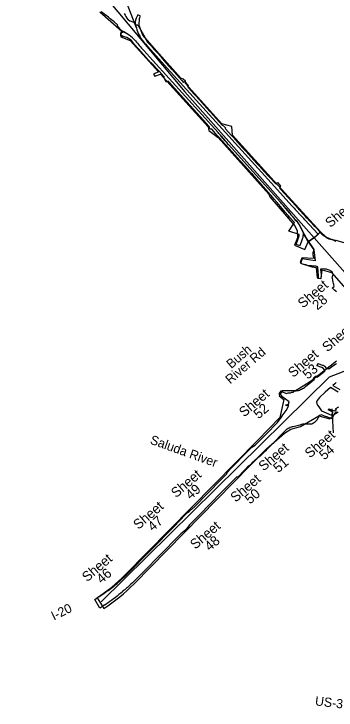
# Model space of a CAD drawing. Extents: x 1944182 to 1978751, y 789830 to 827717.
# Drawn here: x 1953823 to 1964336, y 789830 to 812550 of the extents above; entities that cross this region are included whole.
import ezdxf

# ---------------------------------------------------------------- set-up
doc = ezdxf.new("R2010")
doc.units = 0
for name, color, linetype in [('Default', 7, 'Continuous'), ('RD_AR_03', 7, 'Continuous'), ('RD_AR_04', 7, 'Continuous'), ('RD_AR_05', 7, 'Continuous'), ('RD_SHT_ID', 7, 'Continuous'), ('RD_SHT_Misc4', 7, 'Continuous')]:
    doc.layers.add(name, color=color, linetype=linetype)

msp = doc.modelspace()

# ---------------------------------------------------------------- linework, layer by layer
at = {"layer": 'Default'}
for points in [[(1964345, 803483), (1964330, 803497), (1964283, 803539), (1964264, 803556), (1964209, 803606), (1964271, 803655), (1964258, 803721), (1964252, 803748), (1964243, 803793), (1964239, 803809), (1964235, 803831), (1964230, 803856), (1964216, 803922), (1964213, 803938), (1964222, 803977), (1964238, 804046), (1964243, 804065), (1964231, 804078), (1964218, 804091), (1964219, 804117), (1964197, 804135), (1964170, 804154), (1964141, 804171), (1964112, 804186), (1964082, 804199), (1964050, 804209), (1964045, 804210), (1964018, 804217), (1963986, 804222), (1963953, 804225), (1963920, 804226), (1963887, 804224), (1963854, 804220), (1963830, 804215), (1963844, 804036), (1963845, 804010), (1963844, 803984), (1963841, 803958), (1963832, 803904), (1963752, 803910), (1963762, 803970), (1963764, 803990), (1963765, 804010), (1963765, 804010), (1963764, 804029), (1963755, 804138), (1963743, 804293), (1963673, 804320), (1963643, 804320), (1963643, 804320), (1963618, 804320), (1963563, 804322), (1963537, 804324), (1963509, 804327), (1963458, 804334), (1963454, 804334), (1963401, 804344), (1963379, 804349), (1963347, 804356), (1963294, 804370), (1963242, 804387), (1963191, 804406), (1963204, 804441), (1963204, 804442), (1963179, 804452), (1963230, 804604), (1963401, 804592), (1963624, 804575), (1963613, 804599), (1963604, 804623), (1963597, 804648), (1963592, 804673), (1963589, 804698), (1963588, 804724), (1963589, 804738), (1963590, 804750), (1963592, 804765), (1963593, 804775), (1963599, 804801), (1963607, 804825), (1963615, 804850), (1963619, 804865), (1963394, 805197), (1963391, 805201), (1963287, 805354), (1963268, 805382), (1963261, 805363), (1963259, 805330), (1963259, 805329), (1963255, 805296), (1963250, 805263), (1963248, 805256), (1963243, 805230), (1963234, 805197), (1963223, 805165), (1963156, 804983), (1963127, 804994), (1963070, 805014), (1963034, 805028), (1963101, 805210), (1963112, 805244), (1963120, 805278), (1963126, 805313), (1963130, 805348), (1962797, 805460), (1962974, 805742), (1962819, 805913), (1962789, 805947), (1962759, 805982), (1962760, 805982), (1962673, 806084), (1962521, 806262), (1962408, 806394), (1962315, 806503), (1962215, 806620), (1962176, 806666), (1962137, 806712), (1962122, 806729), (1962067, 806793), (1962035, 806831), (1962031, 806835), (1961892, 806994), (1961888, 806999), (1961876, 807013), (1961866, 807024), (1961853, 807039), (1961839, 807055), (1961827, 807067), (1961812, 807085), (1961797, 807102), (1961777, 807124), (1961748, 807157), (1961603, 807318), (1961567, 807358), (1961530, 807399), (1961476, 807459), (1961430, 807510), (1961380, 807565), (1961220, 807741), (1961109, 807865), (1961041, 807939), (1960517, 808519), (1960516, 808520), (1960458, 808584), (1960278, 808784), (1960242, 808786), (1960198, 808835), (1960200, 808870), (1960183, 808888), (1960011, 809078), (1960009, 809081), (1959467, 809680), (1959462, 809685), (1958977, 810222), (1958945, 810257), (1958939, 810263), (1958859, 810352), (1958812, 810329), (1958789, 810319), (1958712, 810475), (1958734, 810487), (1958736, 810488), (1958611, 810627), (1958601, 810637), (1958581, 810659), (1958560, 810682), (1958558, 810684), (1958544, 810700), (1958505, 810740), (1958365, 810883), (1958325, 810926), (1958323, 810928), (1958285, 810969), (1958060, 811217), (1958033, 811248), (1958030, 811251), (1957988, 811297), (1957967, 811320), (1957901, 811395), (1957873, 811426), (1957760, 811557), (1957728, 811594), (1957649, 811689), (1957503, 811783), (1957468, 811795), (1957433, 811805), (1957396, 811812), (1957359, 811817), (1957361, 811834), (1957338, 811837), (1957315, 811839), (1957317, 811936), (1957405, 811961), (1957377, 811979), (1957349, 811998), (1957323, 812020), (1957299, 812043), (1957275, 812067), (1957254, 812093), (1957234, 812120), (1957215, 812148), (1957202, 812195), (1957093, 812289), (1957093, 812289), (1956969, 812394), (1956908, 812446), (1956909, 812446), (1956670, 812621)], [(1957421, 812560), (1957448, 812511), (1957477, 812462), (1957507, 812415), (1957510, 812411), (1957539, 812368), (1957539, 812368), (1957558, 812357), (1957605, 812328), (1957616, 812321), (1957616, 812321), (1957776, 812259), (1957776, 812259), (1957776, 812259), (1957776, 812257), (1957775, 812233), (1957775, 812227), (1957777, 812191), (1957865, 812191), (1958047, 811871), (1958134, 811704), (1958185, 811631), (1958260, 811548), (1958297, 811508), (1958367, 811430), (1958383, 811411), (1958437, 811352), (1958537, 811242), (1958574, 811201), (1958594, 811178), (1958613, 811157), (1958643, 811121), (1958651, 811113), (1958685, 811072), (1958779, 810959), (1958815, 810917), (1958849, 810879), (1958853, 810875), (1958882, 810842), (1958979, 810735), (1958982, 810732), (1958983, 810731), (1959049, 810658), (1959303, 810377), (1959359, 810315), (1959359, 810315), (1959380, 810335), (1959396, 810349), (1959521, 810210), (1959484, 810177), (1959539, 810116), (1959601, 810047), (1959730, 809905), (1959887, 809731), (1959951, 809660), (1959952, 809660), (1960021, 809583), (1960219, 809364), (1960224, 809368), (1960260, 809320), (1960325, 809247), (1960620, 808921), (1960662, 808900), (1960727, 808829), (1960718, 808812), (1960924, 808585), (1960975, 808529), (1961297, 808173), (1961298, 808172), (1961330, 808137), (1961341, 808124), (1961403, 808056), (1961552, 807890), (1961760, 807660), (1961866, 807544), (1961870, 807539), (1961931, 807472), (1961960, 807440), (1961998, 807398), (1962000, 807397), (1962101, 807289), (1962185, 807200), (1962245, 807136), (1962286, 807092), (1962370, 807004), (1962375, 806998), (1962375, 806998), (1962426, 807044), (1962500, 806964), (1962524, 806938), (1962497, 806877), (1962503, 806857), (1962667, 806676), (1962773, 806559), (1962773, 806558), (1962812, 806516), (1962830, 806496), (1962905, 806413), (1963012, 806295), (1963089, 806209), (1963136, 806157), (1963138, 806156), (1963190, 806098), (1963193, 806095), (1963234, 806049), (1963241, 806041), (1963272, 806008), (1963289, 805989), (1963310, 805967), (1963354, 805920), (1963401, 805870), (1963455, 805812), (1963511, 805751), (1963551, 805708), (1963579, 805677), (1963646, 805603), (1963654, 805609), (1963689, 805568), (1963692, 805566), (1963731, 805521), (1963787, 805456), (1963808, 805432), (1963839, 805398), (1963871, 805366), (1963905, 805336), (1963923, 805322), (1963941, 805307), (1963978, 805281), (1964006, 805264), (1964017, 805257), (1964057, 805235), (1964098, 805215), (1964140, 805198), (1964183, 805183), (1964198, 805195), (1964322, 805139), (1964332, 805162), (1964626, 805081)], [(1964338, 799563), (1964320, 799548), (1964304, 799532), (1964290, 799514), (1964277, 799494), (1964266, 799474), (1964246, 799431), (1964204, 799340), (1964170, 799352), (1964168, 799347), (1964063, 799385), (1963958, 799426), (1963855, 799468), (1963788, 799442), (1963763, 799386), (1963749, 799357), (1963734, 799330), (1963716, 799304), (1963697, 799279), (1963676, 799256), (1963653, 799234), (1963629, 799214), (1963604, 799195), (1963577, 799178), (1963550, 799163), (1963363, 799165), (1963359, 799165), (1963277, 799162), (1963236, 799161), (1963208, 799149), (1963179, 799138), (1963150, 799129), (1962937, 799079), (1962902, 799071), (1962867, 799061), (1962833, 799049), (1962800, 799034), (1962768, 799017), (1962737, 798999), (1962708, 798978), (1962570, 798838), (1962313, 798576), (1962104, 798364), (1962103, 798363), (1962021, 798280), (1961963, 798221), (1961927, 798185), (1961889, 798149), (1961858, 798121), (1961851, 798115), (1961588, 797884), (1961538, 797838), (1961489, 797790), (1961481, 797797), (1961360, 797675), (1961344, 797658), (1961125, 797435), (1961098, 797445), (1961086, 797432), (1960926, 797270), (1960923, 797266), (1960610, 796948), (1960209, 796540), (1959902, 796229), (1959551, 795871), (1959428, 795711), (1959270, 795586), (1959016, 795328), (1959011, 795323), (1958798, 795106), (1958429, 794730), (1958221, 794518), (1957905, 794197), (1957862, 794154), (1957748, 794037), (1957694, 793986), (1957641, 793936), (1957586, 793885), (1957532, 793836), (1957500, 793808), (1957476, 793787), (1957437, 793753), (1957420, 793739), (1957370, 793697), (1957364, 793691), (1957307, 793644), (1957249, 793598), (1957192, 793552), (1957133, 793507), (1957122, 793498), (1957074, 793462), (1957015, 793418), (1956955, 793375), (1956895, 793332), (1956834, 793291), (1956787, 793259), (1956773, 793249), (1956711, 793209), (1956649, 793169), (1956631, 793157), (1956459, 793439), (1956505, 793467), (1956549, 793495), (1956558, 793501), (1956573, 793511), (1956598, 793527), (1956642, 793558), (1956657, 793568), (1956687, 793589), (1956752, 793636), (1956787, 793660), (1956793, 793664), (1956799, 793668), (1956815, 793678), (1956859, 793707), (1956902, 793736), (1956944, 793766), (1956986, 793796), (1957028, 793827), (1957069, 793859), (1957094, 793878), (1957109, 793891), (1957119, 793898), (1957149, 793924), (1957189, 793957), (1957228, 793991), (1957251, 794012), (1957266, 794026), (1957500, 794240), (1957503, 794242), (1957497, 794247), (1958310, 795073), (1959040, 795816), (1959081, 795857), (1959112, 795888), (1959161, 795939), (1959492, 796275), (1959540, 796315), (1959675, 796428), (1959689, 796440), (1959781, 796533), (1959877, 796631), (1959967, 796722), (1960023, 796779), (1960056, 796813), (1960220, 796979), (1960526, 797290), (1960644, 797410), (1960739, 797507), (1960785, 797554), (1960759, 797563), (1960761, 797565), (1960949, 797756), (1960969, 797777), (1961385, 798199), (1961591, 798408), (1961694, 798478), (1961695, 798478), (1962039, 798829), (1962419, 799215), (1962574, 799426), (1962580, 799434), (1962644, 799520), (1962705, 799604), (1962792, 799769), (1962782, 799775), (1962704, 799755), (1962697, 799782), (1962695, 799789), (1962786, 799812), (1962802, 799891), (1962569, 800069), (1962568, 800069), (1962563, 800073), (1962571, 800085), (1962541, 800104), (1962478, 800144), (1962541, 800249), (1962570, 800231), (1962571, 800231), (1962706, 800164), (1962773, 800187), (1962810, 800187), (1962852, 800188), (1962873, 800197), (1962893, 800204), (1962915, 800209), (1962937, 800211), (1962959, 800212), (1962960, 800247), (1962996, 800248), (1963004, 800248), (1963033, 800251), (1963070, 800256), (1963106, 800265), (1963141, 800275), (1963175, 800288), (1963182, 800291), (1963209, 800304), (1963241, 800321), (1963272, 800341), (1963302, 800363), (1963338, 800392), (1963401, 800442), (1963540, 800553), (1963571, 800577), (1963571, 800577), (1963637, 800630), (1963600, 800676), (1963684, 800742), (1963716, 800693), (1963882, 800825), (1963914, 800850), (1963938, 800870), (1963939, 800871), (1963967, 800893), (1963965, 800925), (1963900, 800997), (1963891, 801005), (1963881, 801012), (1963870, 801016), (1963839, 801026), (1963716, 801068), (1963717, 801071), (1963719, 801078), (1963740, 801135), (1963738, 801135), (1963741, 801144), (1963743, 801143), (1963895, 801092), (1963913, 801085), (1963930, 801075), (1963945, 801064), (1963959, 801050), (1964023, 800979), (1964060, 800976), (1964099, 800972), (1964182, 801029), (1964266, 801085), (1964351, 801138)], [(1964341, 800523), (1964290, 800479), (1964235, 800428), (1964453, 800295)], [(1964401, 800211), (1964154, 800356), (1963985, 800203), (1963795, 800031), (1963761, 799989), (1963755, 799981), (1963729, 799946), (1963697, 799902), (1963698, 799894), (1963699, 799882), (1963704, 799856), (1963711, 799830), (1963719, 799805), (1963730, 799781), (1963768, 799727), (1963858, 799597), (1964014, 799532), (1964185, 799459), (1964207, 799503), (1964218, 799525), (1964232, 799546), (1964228, 799558), (1964079, 799627), (1964108, 799662), (1964175, 799634), (1964272, 799594), (1964293, 799612), (1964315, 799628), (1964320, 799622), (1964349, 799641), (1964332, 799669), (1964424, 799727)]]:
    msp.add_lwpolyline(points, dxfattribs=at)
at = {"layer": 'RD_AR_03'}
for p, q in [((1963832, 805435), (1963612, 805240)), ((1963849, 805416), (1963832, 805435)), ((1963612, 805240), (1963430, 805114)), ((1963430, 805114), (1963608, 804856)), ((1964698, 805062), (1964234, 805178)), ((1963608, 804856), (1963657, 804491)), ((1963234, 804554), (1963174, 804418)), ((1963657, 804491), (1963234, 804554)), ((1963174, 804418), (1963548, 804298)), ((1963548, 804298), (1963691, 804274)), ((1963691, 804274), (1963722, 803935)), ((1963847, 803917), (1963886, 804194)), ((1963886, 804194), (1964181, 804107)), ((1964181, 804107), (1965182, 802966)), ((1963722, 803935), (1963847, 803917)), ((1964351, 801214), (1963931, 800887)), ((1963931, 800887), (1963532, 800575)), ((1963532, 800575), (1963262, 800396)), ((1963011, 800253), (1962574, 800251)), ((1963262, 800396), (1963011, 800253)), ((1964312, 799507), (1964402, 799559)), ((1963178, 799089), (1963768, 799434)), ((1963768, 799434), (1964129, 799337)), ((1962857, 799003), (1963178, 799089)), ((1962069, 798352), (1962655, 798872)), ((1962655, 798872), (1962857, 799003)), ((1961778, 798638), (1957453, 794242)), ((1957744, 793955), (1962069, 798352)), ((1956534, 793496), (1956760, 793149))]:
    msp.add_line(p, q, dxfattribs=at)
for points in [[(1962574, 800251), (1962482, 800090), (1962635, 799963), (1962501, 799374), (1961778, 798638)], [(1964129, 799337), (1964272, 799469), (1964312, 799507)]]:
    msp.add_lwpolyline(points, dxfattribs=at)
for centre, radius, start, end in [((1964452, 805961), 813, 222.1319, 254.4218), ((1953712, 797914), 5242, 302.5651, 315.5254), ((1953670, 797925), 5688, 302.8981, 315.737)]:
    msp.add_arc(centre, radius, start, end, dxfattribs=at)
at = {"layer": 'RD_AR_04'}
for p, q in [((1957869, 812522), (1957844, 812479)), ((1957956, 812474), (1957869, 812522)), ((1957931, 812430), (1957956, 812474)), ((1957914, 812171), (1957919, 812407)), ((1957780, 812209), (1957822, 812097)), ((1958032, 811861), (1957914, 812171)), ((1957327, 811994), (1957307, 811799)), ((1957307, 811799), (1957615, 811679)), ((1958479, 811350), (1958032, 811861)), ((1957615, 811679), (1958537, 810662)), ((1958353, 811034), (1958058, 811360)), ((1958192, 811482), (1958825, 810783)), ((1959270, 810448), (1958479, 811350)), ((1960484, 808678), (1958353, 811034)), ((1958537, 810662), (1958373, 810579)), ((1958825, 810783), (1960618, 808801)), ((1958373, 810579), (1958424, 810520)), ((1958424, 810520), (1958602, 810589)), ((1958602, 810589), (1960163, 808868)), ((1959351, 810417), (1959270, 810448)), ((1959423, 810356), (1959351, 810417)), ((1959422, 810278), (1959423, 810356)), ((1960613, 808960), (1959422, 810278)), ((1960163, 808868), (1960184, 808746)), ((1960930, 808879), (1960613, 808960)), ((1960961, 808593), (1960930, 808879)), ((1960184, 808746), (1960490, 808520)), ((1960618, 808801), (1962322, 806918)), ((1962312, 807096), (1960961, 808593)), ((1960490, 808520), (1962142, 806670)), ((1960719, 808404), (1960590, 808557)), ((1962522, 806407), (1960824, 808284)), ((1963832, 805435), (1962312, 807096)), ((1962142, 806670), (1962173, 806579)), ((1962173, 806579), (1962992, 805638)), ((1962822, 806047), (1962696, 806203)), ((1963038, 806130), (1963177, 805986)), ((1962992, 805638), (1963071, 805469)), ((1963072, 805760), (1962995, 805845)), ((1963317, 805835), (1963747, 805360)), ((1963071, 805469), (1963080, 805246)), ((1963430, 805114), (1963158, 805636)), ((1963747, 805360), (1963832, 805435)), ((1963080, 805246), (1962980, 805003)), ((1962980, 805003), (1963316, 804865)), ((1963316, 804865), (1963430, 805114))]:
    msp.add_line(p, q, dxfattribs=at)
msp.add_lwpolyline([(1962322, 806918), (1962322, 806917), (1962897, 806282)], dxfattribs=at)
for centre, radius, start, end in [((1958288, 812230), 508, 150.7645, 182.3894), ((1958288, 812230), 408, 150.7645, 154.4314), ((1958834, 812320), 1036, 192.4398, 221.075), ((1956924, 810934), 1134, 40.3149, 69.1784), ((1966628, 819113), 11556, 220.1067, 222.1319), ((1966628, 819113), 11374, 221.075, 222.1319), ((1956907, 805442), 4824, 40.2219, 42.1319), ((1964366, 811488), 4776, 220.2219, 222.1319), ((1958944, 803171), 4824, 38.9423, 42.1319), ((1968106, 810994), 7024, 222.1319, 223.8231), ((1966537, 809049), 4776, 218.9423, 222.1319), ((1958144, 801155), 6976, 42.1319, 43.8231), ((1962636, 805365), 589, 27.4726, 42.1319)]:
    msp.add_arc(centre, radius, start, end, dxfattribs=at)
at = {"layer": 'RD_AR_05'}
for p, q in [((1956625, 812617), (1957342, 811988)), ((1958058, 811360), (1958353, 811034)), ((1958825, 810783), (1958192, 811482)), ((1958353, 811034), (1960484, 808678)), ((1960618, 808801), (1958825, 810783)), ((1962322, 806918), (1960618, 808801)), ((1960590, 808557), (1960719, 808404)), ((1960824, 808284), (1962522, 806407)), ((1962322, 806917), (1962322, 806918)), ((1962897, 806282), (1962322, 806917)), ((1962696, 806203), (1962822, 806047)), ((1963177, 805986), (1963038, 806130)), ((1962995, 805845), (1963072, 805760)), ((1963747, 805360), (1963317, 805835)), ((1963158, 805636), (1963430, 805114)), ((1963430, 805114), (1963612, 805240)), ((1963612, 805240), (1963747, 805360))]:
    msp.add_line(p, q, dxfattribs=at)
msp.add_lwpolyline([(1957822, 812097), (1957780, 812209), (1957425, 813145)], dxfattribs=at)
for centre, radius, start, end in [((1958834, 812320), 1036, 192.4398, 221.075), ((1956924, 810934), 1134, 40.3149, 68.3476), ((1966628, 819113), 11556, 220.1067, 222.1319), ((1966628, 819113), 11374, 221.075, 222.1319), ((1956907, 805442), 4824, 40.2219, 42.1319), ((1964366, 811488), 4776, 220.2219, 222.1319), ((1958944, 803171), 4824, 38.9423, 42.1319), ((1968106, 810994), 7024, 222.1319, 223.8231), ((1966537, 809049), 4776, 218.9423, 222.1319), ((1958144, 801155), 6976, 42.1319, 43.8231), ((1962636, 805365), 589, 27.4726, 42.1319)]:
    msp.add_arc(centre, radius, start, end, dxfattribs=at)
at = {"layer": 'RD_SHT_ID'}
msp.add_line((1964257, 798874), (1964213, 799657), dxfattribs=at)
at = {"layer": 'RD_SHT_Misc4'}
for p, q in [((1953823, 816695), (1959396, 810005)), ((1959396, 810005), (1966734, 801722)), ((1964119, 800706), (1968039, 802236)), ((1956667, 793363), (1964119, 800706))]:
    msp.add_line(p, q, dxfattribs=at)

# ---------------------------------------------------------------- texts
at = {"layer": 'RD_SHT_ID'}
for s, height, rotation, p in [('Sheet', 320, 40.5635, (1964149, 805558)), ('Sheet', 320, 40.5635, (1963255, 802929)), ('28', 320, 40.5635, (1963726, 802868)), ('Sheet', 320, 40.5635, (1964052, 801500)), ('River Rd', 300, 40.5635, (1960881, 800455)), ('Bush', 300, 40.5635, (1960915, 800958)), ('Sheet', 320, 40.5635, (1962937, 800666)), ('53', 320, 40.5635, (1963411, 800608)), ('Sheet', 320, 40.5635, (1961336, 799376)), ('52', 320, 40.5635, (1961808, 799317)), ('Sheet', 320, 40.5635, (1963482, 798036)), ('Saluda River', 300, 340.1606, (1958241, 798531)), ('Sheet', 320, 40.5635, (1961973, 797613)), ('54', 320, 40.5635, (1963950, 797974)), ('51', 320, 40.5635, (1962451, 797558)), ('Sheet', 320, 40.5635, (1959117, 796742)), ('Sheet', 320, 40.5635, (1961056, 796595)), ('49', 320, 40.5635, (1959589, 796682)), ('50', 320, 40.5635, (1961527, 796535)), ('Sheet', 320, 40.5635, (1957885, 795706)), ('47', 320, 40.5635, (1958355, 795646)), ('Sheet', 320, 40.5635, (1959741, 795061)), ('48', 320, 40.5635, (1960212, 795000)), ('Sheet', 320, 40.5635, (1956212, 793998)), ('46', 320, 40.5635, (1956682, 793937)), ('I-20', 300, 26.0667, (1955127, 792751)), ('US-378', 300, 353.2212, (1963637, 789987))]:
    msp.add_text(s, height=height, rotation=rotation, dxfattribs=at).set_placement(p)

doc.saveas('drawing.dxf')
